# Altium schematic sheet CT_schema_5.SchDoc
size 387 x 301 mm
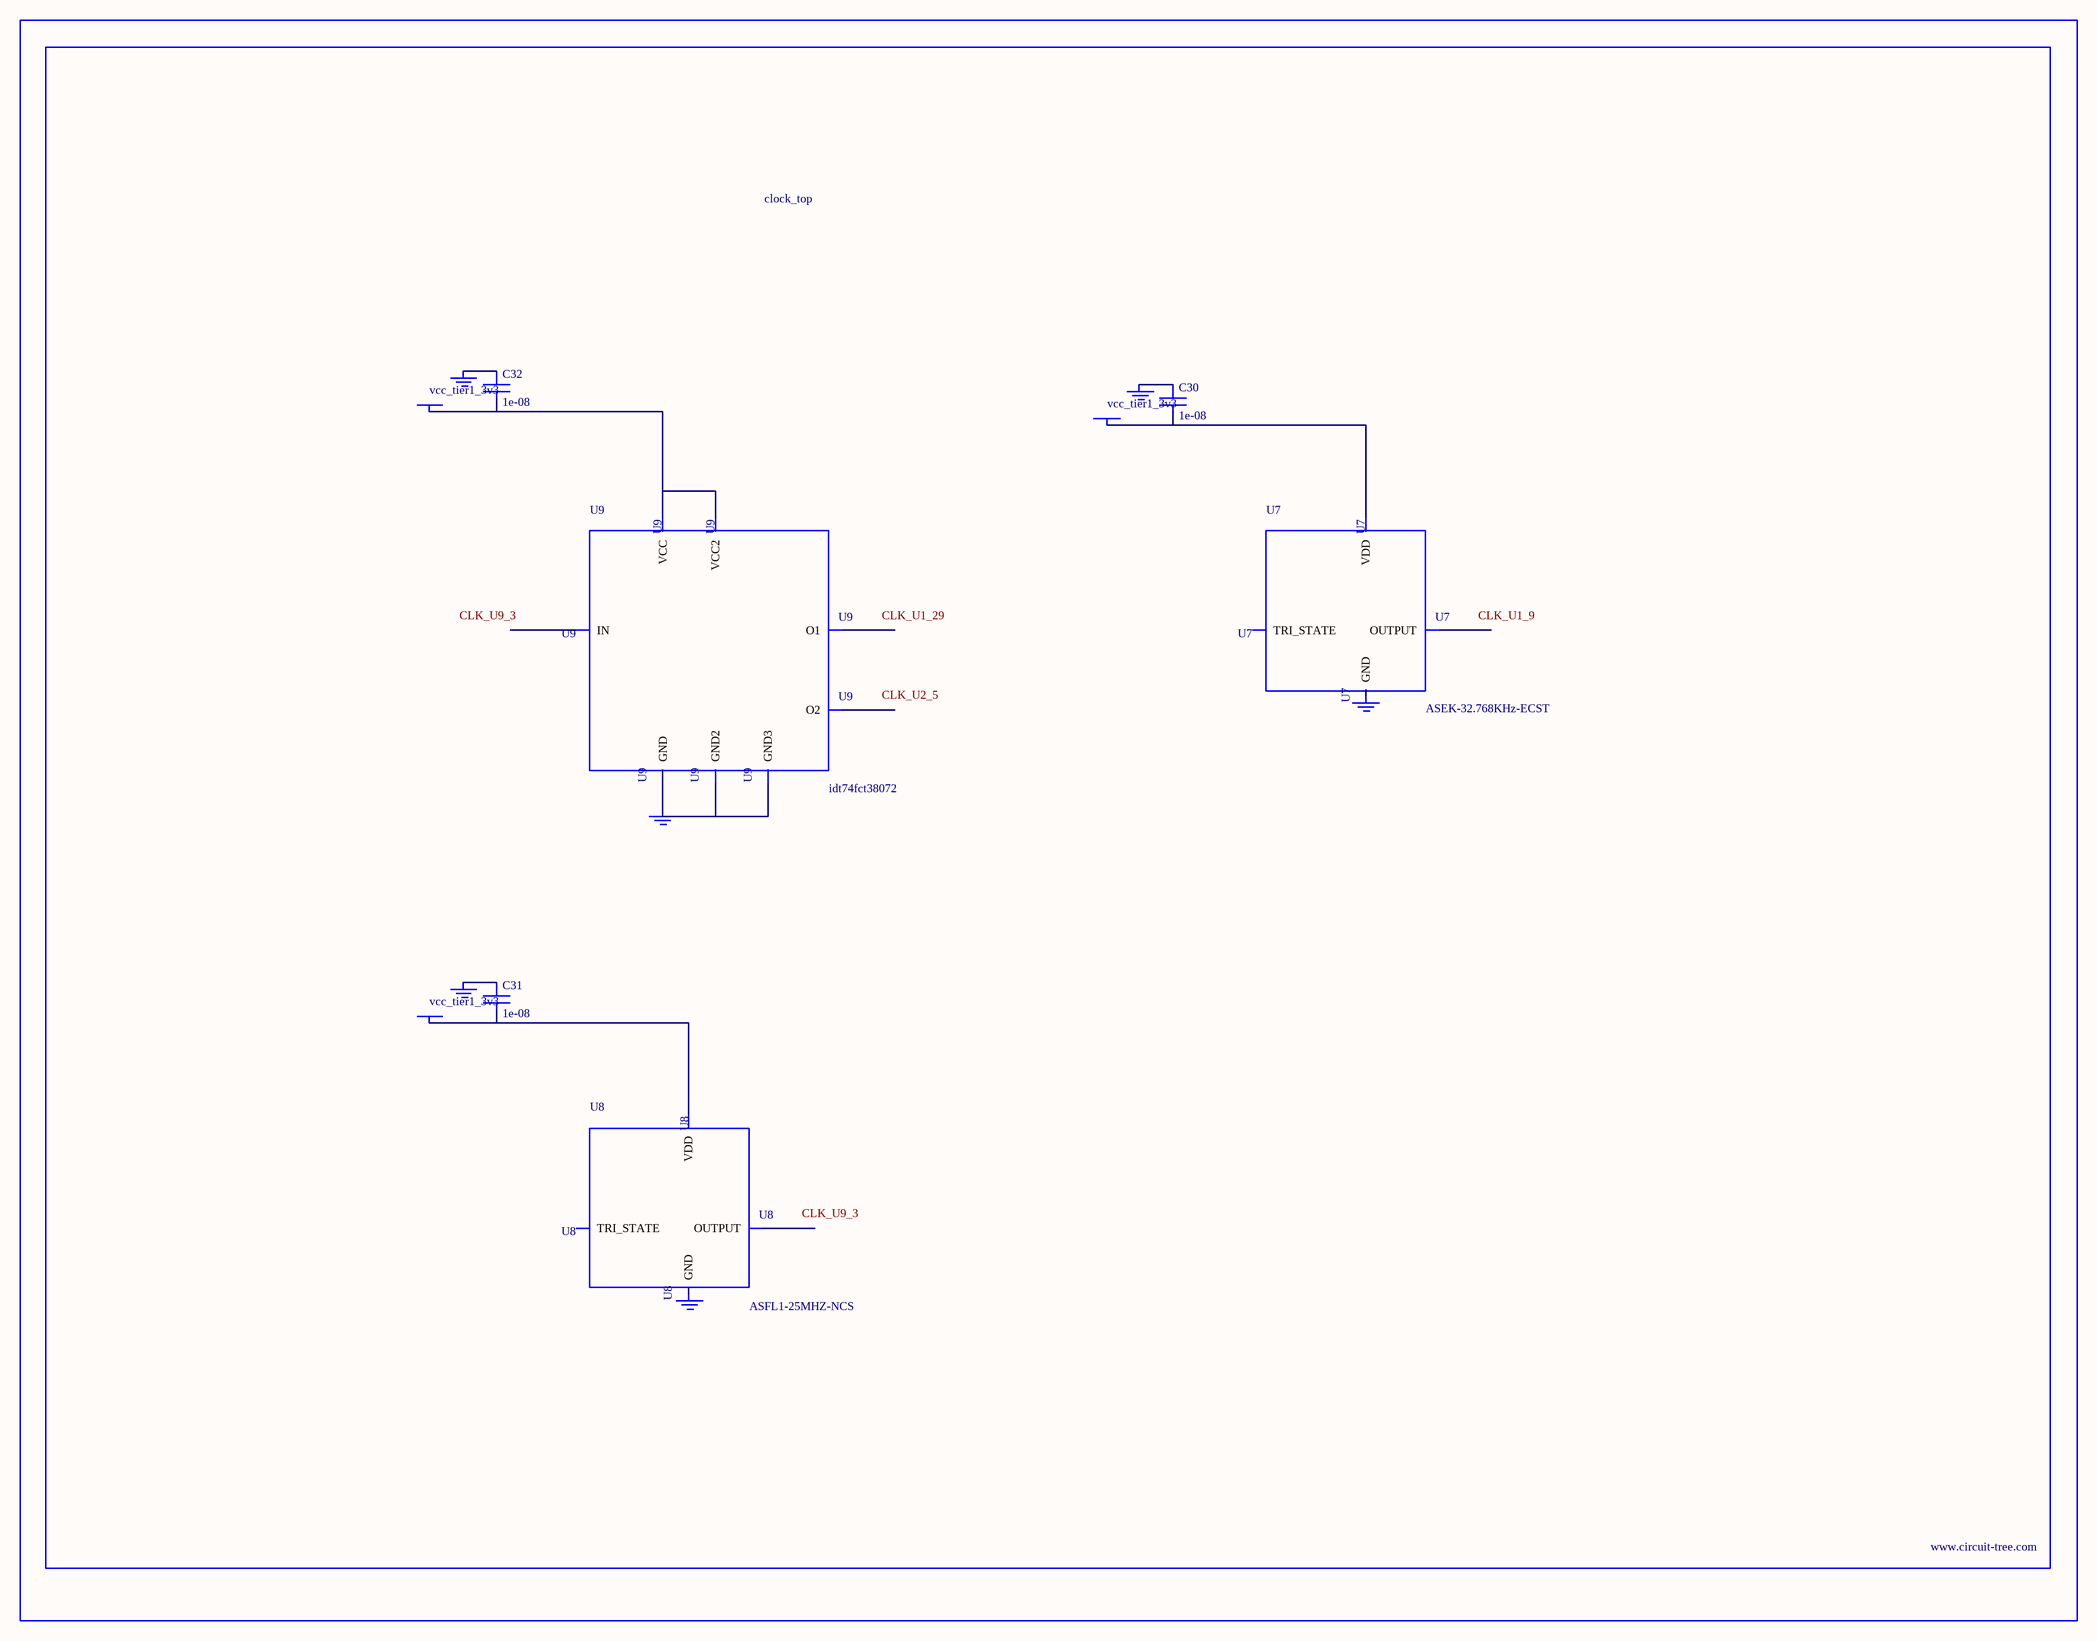
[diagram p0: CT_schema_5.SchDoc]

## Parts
BORDER4  (no value)
C30  1e-08  [C0402]
C31  1e-08  [C0402]
C32  1e-08  [C0402]
GND_INSTANCE_4_0  (no value)
GND_INSTANCE_4_1  (no value)
GND_INSTANCE_4_2  (no value)
GND_INSTANCE_4_3  (no value)
GND_INSTANCE_4_4  (no value)
GND_INSTANCE_4_5  (no value)
POWER_INSTANCE_4_0  vcc_tier1_3v3
POWER_INSTANCE_4_1  vcc_tier1_3v3
POWER_INSTANCE_4_2  vcc_tier1_3v3
U7  ASEK-32.768KHz-ECST  [ASEK]
U8  ASFL1-25MHZ-NCS  [ASFL1]
U9  idt74fct38072  [IDT74FCT38072]

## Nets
NetC30_1: C30.1 GND_INSTANCE_4_0.0(GND)
NetC30_2: C30.2 POWER_INSTANCE_4_0.0(PWR) U7.4(VDD)
NetC31_1: C31.1 GND_INSTANCE_4_2.0(GND)
NetC31_2: C31.2 POWER_INSTANCE_4_1.0(PWR) U8.4(VDD)
NetC32_1: C32.1 GND_INSTANCE_4_4.0(GND)
NetC32_2: C32.2 POWER_INSTANCE_4_2.0(PWR) U9.1(VCC) U9.2(VCC2)
NetGND_INSTANCE_4_5_0: GND_INSTANCE_4_5.0(GND) U9.4(GND) U9.5(GND2) U9.8(GND3)

Not connected (* = marked no-connect by the designer): GND_INSTANCE_4_1 0(GND); GND_INSTANCE_4_3 0(GND); U7 1(TRI_STATE) 2(GND) 3(OUTPUT); U8 1(TRI_STATE) 2(GND) 3(OUTPUT); U9 3(IN) 6(O2) 7(O1)

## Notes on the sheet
- Labels drawn without touching a wire or pin: CLK_U1_9, CLK_U1_29, CLK_U2_5, CLK_U9_3

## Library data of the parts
BORDER4 = BORDER_PAGE4
C30-C32 = C0402C103K3RAC
GND_INSTANCE_4_0-GND_INSTANCE_4_5 = GND
POWER_INSTANCE_4_0-POWER_INSTANCE_4_2 = PWR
